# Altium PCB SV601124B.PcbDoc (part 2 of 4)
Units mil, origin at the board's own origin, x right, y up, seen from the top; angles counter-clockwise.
Board outline 3733 x 2734 mil, 4 copper layers (Top Layer, Mid-Layer 1, Mid-Layer 2, Bottom Layer), stack 60.2 mil thick; 246 components, 169 nets, 780 pads, 426 vias.
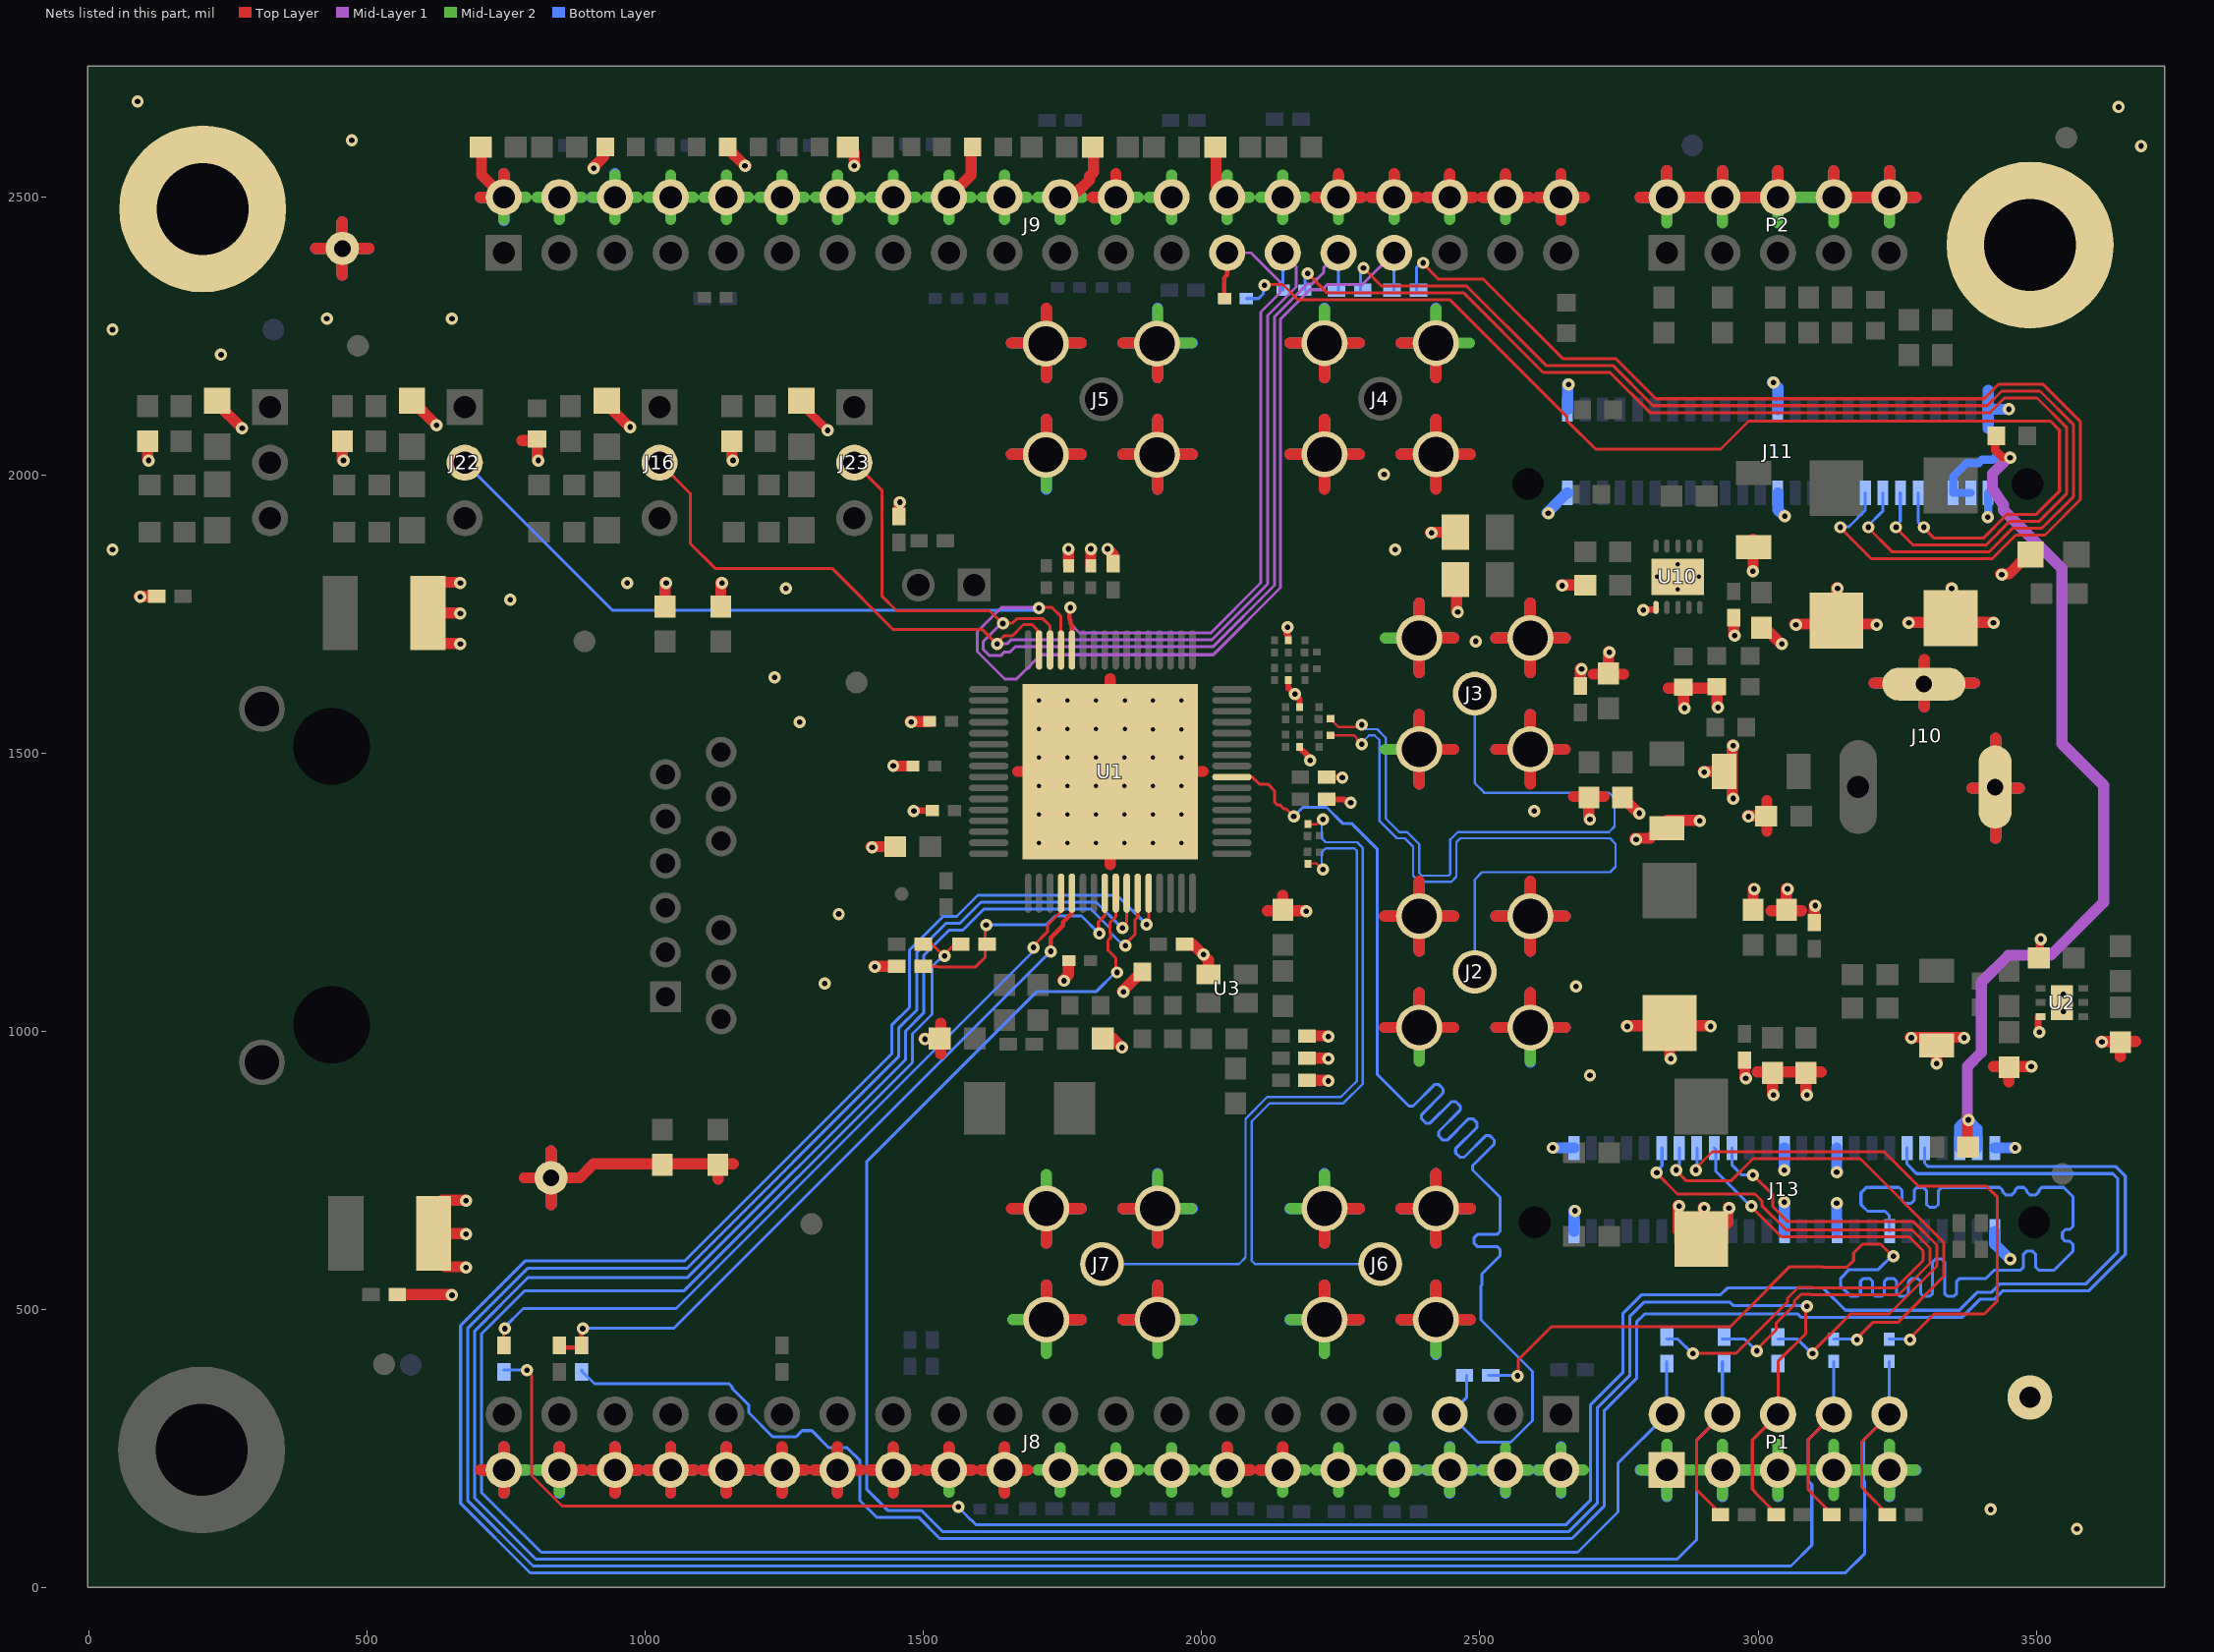
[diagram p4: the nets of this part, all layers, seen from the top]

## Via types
v1: diameter 22, hole 10, Top Layer to Bottom Layer, 385 vias
v2: diameter 19.68, hole 7.87, Top Layer to Bottom Layer, 40 vias
v3: diameter 20, hole 10, Top Layer to Bottom Layer, 1 vias

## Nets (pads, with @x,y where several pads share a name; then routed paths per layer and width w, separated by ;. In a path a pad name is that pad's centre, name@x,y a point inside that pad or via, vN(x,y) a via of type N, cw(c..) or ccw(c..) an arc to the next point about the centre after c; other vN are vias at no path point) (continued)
GND: C7.2 C8.2 C9.2 C10.2 C11.2 C12.1 C14.1 C15.1 C16.1 C17.2 C19.1 C53.2 C62.1 C70.1 C75.1 C80.2 C82.2 C87.1 C89.1 C90.1 C98.2 C104.1 C115.1 C128.2 C129.1 C133.2 C182.1 C183.2 C265.1 C267.1 C269.1 C270.1 C271.1 C272.1 C273.2 C274.2 C318.1 C319.1 C324.1 C325.1 C326.1 C327.1 C328.1 C329.1 C330.1 C331.1 C332.1 J2.2 J2.3 J2.4 J2.5 J3.2 J3.3 J3.4 J3.5 J4.2 J4.3 J4.4 J4.5 J5.2 J5.3 J5.4 J5.5 J6.2 J6.3 J6.4 J6.5 J7.2 J7.3 J7.4 J7.5 J8.2 J8.4 J8.6 J8.8 J8.10 J8.12 J8.14 J8.16 J8.18 J8.20 J8.22 J8.24 J8.26 J8.28 J8.30 J8.32 J8.34 J8.36 J8.38 J8.40 J9.2 J9.4 J9.6 J9.8 J9.10 J9.12 J9.14 J9.16 J9.18 J9.20 J9.22 J9.24 J9.26 J9.28 J9.30 J9.32 J9.34 J9.36 J9.38 J9.40 J10.2 J10.3 J11.1 J11.2 J11.25 J11.26 J11.49 J11.50 J13.1 J13.2 J13.19 J13.20 J13.25 J13.26 J13.49 J13.50 LD3.2 LD17.2 LD22.2 LD23.2 LD24.2 M200.1 M201.1 M202.1 P1.1 P1.3 P1.5 P1.7 P1.9 P2.2 P2.4 P2.6 P2.8 P2.10 pad.0 R2.1 R4.1 R6.1 R8.1 R11.1 R13.1 R16.1 R18.1 R20.1 R21.1 R25.1 R27.1 R29.1 R31.1 R34.1 R87.1 R97.2 R154.2 R177.1 R292.1 R352.2 R641.1 R645.1 R649.1 R661.1 U1.65 U2.3 U2.7 U3.2 U10.6 U10.11 | length 39013.7
  Top Layer w11: v1@1481,1397 C330.1@1516,1397 ; v1@2152.77,1727.22 2152.77,1715.01 2156,1711.78 R27.1@2156,1701.3 ; R29.1@2156,1632.7 2156,1617 2166,1607 2176,1597 R31.1@2176,1581.3 ; R34.1@2176,1512.7 2176,1510.24 2189.5,1496.74 2189.5,1494.72 2191,1493.22 2191,1490.45 v1@2193.45,1488 ; C327.1@2221,1417 2256,1417 2261,1412 v1@2266,1412 ; C328.1@2221,1457 v1@2251,1457 ; v1@2791.94,1757.94 U10.6@2816.63,1757.94
  Top Layer w12: v1@3503.47,999.53 U2.3@3503.47,1026.4
  Top Layer w15: LD23.2@1281,2133.34 1281,2127 v1(1328,2080) ; C129.1@3506,1132 v1@3506,1167
  Top Layer w20: v1@91,1782 R154.2@122.38,1782 ; v1@106,2027 R25.1@106,2062 ; LD24.2@231,2128 v1@274,2085 ; 407.98,2407 pad.0@456,2407 ; v1@456,2027 R18.1@456,2062 ; 456,2358.98 pad.0@456,2407 ; 456,2455.02 pad.0@456,2407 ; 504.02,2407 pad.0@456,2407 ; R352.2@554.62,527 v1@651,527 ; LD22.2@581,2132 LD22.2@581,2132.98 ; LD22.2@581,2133.34 v1(625,2089.34) ; v1@666,1697 626,1697 611.71,1711.29 C19.1@611.71,1752 ; v1@666,1752 C19.1@611.71,1752 ; v1@666,1807 631,1807 611.71,1787.71 C19.1@611.71,1752 ; v1@676,577 641,577 621.71,596.29 C115.1@621.71,637 ; v1@676,637 C115.1@621.71,637 ; v1@676.14,696.86 635.86,696.86 621.71,682.71 C115.1@621.71,637 ; 703.95,212 J8.40@746,212 ; 703.95,2499 J9.2@746,2499 ; R2.1@706,2589 706,2539 J9.2@746,2499 ; 746,169.95 J8.40@746,212 ; 746,254.05 J8.40@746,212 ; 746,2541.05 J9.2@746,2499 ; 778.48,2062 806,2062 v1@806,2027 ; 782.98,737 pad.0@831,737 ; 831,688.98 pad.0@831,737 ; 831,785.02 pad.0@831,737 ; 846,254.05 J8.38@846,212 888.05,212 ; 903.95,212 J8.36@946,212 ; v1@906,2552 926,2572 R4.1@926,2589 ; LD3.2@931,2127 v1@971,2087 ; 946,169.95 J8.36@946,212 ; 946,254.05 J8.36@946,212 ; 988.05,212 J8.36@946,212 ; 1003.95,212 J8.34@1046,212 ; C9.2@1036,1762 v1@1036,1807 ; 1046,169.95 J8.34@1046,212 ; 1046,254.05 J8.34@1046,212 ; 1088.05,212 J8.34@1046,212 ; 1103.95,212 J8.32@1146,212 ; 1131,734.48 C7.2@1131,762 ; C10.2@1136,1762 v1@1136,1807 ; 1146,169.95 J8.32@1146,212 ; 1146,254.05 J8.32@1146,212 ; R6.1@1146,2589 v1(1179.47,2555.53) v1@1181,2555.53 ; v1@1156,2027 R21.1@1156,2062 ; 1158.52,762 C7.2@1131,762 ; 1188.05,212 J8.32@1146,212 ; 1203.95,212 J8.30@1246,212 ; 1246,169.95 J8.30@1246,212 ; 1246,254.05 J8.30@1246,212 ; 1288.05,212 J8.30@1246,212 ; 1303.95,212 J8.28@1346,212 ; 1346,169.95 J8.28@1346,212 ; 1346,254.05 J8.28@1346,212 ; R8.1@1366,2589 1376,2579 v1(1376,2555.53) ; 1388.05,212 J8.28@1346,212 ; 1403.95,212 J8.26@1446,212 ; v1@1406,1332 R645.1@1451,1332 ; v1@1411,1117 C319.1@1456,1117 ; 1446,169.95 J8.26@1446,212 ; 1446,254.05 J8.26@1446,212 ; v1(1446,1477) C331.1@1481,1477 ; R661.1@1456,1922 v1@1456,1952 ; v1@1476,1557 C332.1@1511,1557 ; 1488.05,212 J8.26@1446,212 ; v1@1501,987 C273.2@1531,987 ; 1503.95,212 J8.24@1546,212 ; 1531,959.48 C273.2@1531,987 ; 1531,1014.52 C273.2@1531,987 ; 1546,254.05 J8.24@1546,212 ; J9.18@1546,2499 1586,2539 R11.1@1586,2589 ; 1588.05,212 J8.24@1546,212 ; 1603.95,212 J8.22@1646,212 ; 1646,169.95 J8.22@1646,212 ; 1646,254.05 J8.22@1646,212 ; 1658.48,682 J7.2@1721,682 ; 1658.48,2037 J5.3@1721,2037 ; 1658.48,2237 J5.2@1721,2237 ; 1670,1467 U1.65@1836,1467 ; 1688.05,212 J8.22@1646,212 ; 1721,544.52 J7.3@1721,482 1783.52,482 ; 1721,619.48 J7.2@1721,682 ; 1721,2099.52 J5.3@1721,2037 ; 1721,2174.48 J5.2@1721,2237 ; 1721,2299.52 J5.2@1721,2237 ; J9.22@1746,2499 1761.23,2499 1769.8,2507.57 1774.76,2507.57 1781.19,2514 1782.6,2514 1799,2530.4 1799,2536.77 1806,2543.77 R13.1@1806,2589 ; v1@1751,1092 1761,1102 C325.1@1761,1127 ; C318.1@1761,1837 v1(1761,1867) ; 1783.52,682 J7.2@1721,682 ; 1783.52,2037 J5.3@1721,2037 ; 1783.52,2237 J5.2@1721,2237 ; C324.1@1801,1837 v1(1801,1867) ; 1803.95,2499 J9.24@1846,2499 1846,2541.05 ; C274.2@1821,987 1841,987 1855,973 v1@1855,972 ; v1(1831,1867) 1841,1857 C329.1@1841,1837 ; 1836,1300 U1.65@1836,1467 ; 1836,1634 U1.65@1836,1467 ; v1@1857.53,1072 R649.1@1891,1105.47 ; 1858.48,482 J7.4@1921,482 1921,544.52 ; 1858.48,682 J7.5@1921,682 1921,619.48 ; 1858.48,2037 J5.4@1921,2037 ; 1858.48,2237 1921,2237 1921,2174.48 ; 1921,1974.48 J5.4@1921,2037 ; 1921,2099.52 J5.4@1921,2037 ; C326.1@1966,1157 1983.79,1157 2001.3,1139.49 2012.5,1128.29 U3.2@2012.5,1102.51 ; 1983.52,2037 J5.4@1921,2037 ; 2003,1467 U1.65@1836,1467 ; R292.1@2026,2589 2026,2519 J9.28@2046,2499 ; 2046,254.05 J8.14@2046,212 2088.05,212 ; 2103.95,212 J8.12@2146,212 2146,254.05 ; 2118.48,1217 R97.2@2146,1217 ; 2146,1244.52 R97.2@2146,1217 ; 2158.48,2037 J4.3@2221,2037 ; 2158.48,2237 J4.2@2221,2237 ; C271.1@2186,912 v1@2226,912 ; C272.1@2186,952 v1@2226,952 ; C270.1@2186,992 v1@2226,992 ; v1@2186,1217 R97.2@2146,1217 ; 2203.95,2499 J9.32@2246,2499 ; 2221,544.52 J6.3@2221,482 2283.52,482 ; 2221,619.48 J6.2@2221,682 2283.52,682 ; 2221,1974.48 J4.3@2221,2037 ; 2221,2099.52 J4.3@2221,2037 ; 2221,2174.48 J4.2@2221,2237 ; 2246,2541.05 J9.32@2246,2499 ; 2283.52,2037 J4.3@2221,2037 ; 2283.52,2237 J4.2@2221,2237 ; 2288.05,2499 J9.32@2246,2499 ; 2303.95,2499 J9.34@2346,2499 ; 2328.48,1007 J2.3@2391,1007 ; 2328.48,1207 J2.2@2391,1207 ; 2346,2541.05 J9.34@2346,2499 ; 2358.48,482 J6.4@2421,482 ; 2358.48,682 J6.5@2421,682 ; 2358.48,2037 J4.4@2421,2037 ; 2358.48,2237 J4.5@2421,2237 2421,2174.48 ; 2388.05,2499 J9.34@2346,2499 ; 2391,1069.52 J2.3@2391,1007 ; 2391,1144.48 J2.2@2391,1207 ; 2391,1269.52 J2.2@2391,1207 ; 2391,1444.48 J3.3@2391,1507 ; 2391,1569.52 J3.3@2391,1507 ; 2391,1644.48 J3.2@2391,1707 ; 2391,1769.52 J3.2@2391,1707 ; 2403.95,2499 J9.36@2446,2499 ; v1@2411,1897 C87.1@2458.52,1897 ; 2421,544.52 J6.4@2421,482 ; 2421,619.48 J6.5@2421,682 ; 2421,744.52 J6.5@2421,682 ; 2421,1974.48 J4.4@2421,2037 ; 2421,2099.52 J4.4@2421,2037 ; 2446,2541.05 J9.36@2446,2499 ; 2453.52,1007 J2.3@2391,1007 ; 2453.52,1207 J2.2@2391,1207 ; 2453.52,1507 J3.3@2391,1507 ; 2453.52,1707 J3.2@2391,1707 ; v1@2458.52,1754.48 C98.2@2458.52,1812 ; 2483.52,482 J6.4@2421,482 ; 2483.52,682 J6.5@2421,682 ; 2483.52,2037 J4.4@2421,2037 ; 2488.05,2499 J9.36@2446,2499 ; 2503.95,2499 J9.38@2546,2499 ; 2528.48,1007 J2.4@2591,1007 ; 2528.48,1207 J2.5@2591,1207 ; 2528.48,1507 J3.4@2591,1507 ; 2528.48,1707 J3.5@2591,1707 ; 2546,2541.05 J9.38@2546,2499 ; 2588.05,2499 J9.38@2546,2499 ; 2591,1069.52 J2.4@2591,1007 ; 2591,1144.48 J2.5@2591,1207 ; 2591,1269.52 J2.5@2591,1207 ; 2591,1444.48 J3.4@2591,1507 ; 2591,1569.52 J3.4@2591,1507 ; 2591,1644.48 J3.5@2591,1707 ; 2591,1769.52 J3.5@2591,1707 ; 2603.95,2499 J9.40@2646,2499 ; v1@2646,1802 R20.1@2691,1802 ; 2646,2456.95 J9.40@2646,2499 ; 2646,2541.05 J9.40@2646,2499 ; 2653.52,1007 J2.4@2591,1007 ; 2653.52,1207 J2.5@2591,1207 ; 2653.52,1507 J3.4@2591,1507 ; 2653.52,1707 J3.5@2591,1707 ; 2668.48,1422 C265.1@2696,1422 ; C269.1@2681,1617 v1@2681,1652 ; 2688.05,2499 J9.40@2646,2499 ; v1@2696,1382 C265.1@2696,1422 ; 2703.48,1642 C267.1@2731,1642 ; 2723.52,1422 C265.1@2696,1422 ; v1@2731,1682 C267.1@2731,1642 ; C53.2@2756,1422 2766,1412 2766,1411 2784,1393 v1@2785,1393 ; 2758.52,1642 C267.1@2731,1642 ; v1@2763.01,1009.99 C17.2@2841,1009.99 ; v1@2779,1346 2779,1347 2806,1347 2836,1377 2836,1379.48 v1@2893.52,1379.48 ; 2787.98,2499 P2.2@2836,2499 ; 2836,2547.02 P2.2@2836,2499 ; 2838.48,1617 C104.1@2866,1617 ; v1@2841,952 C17.2@2841,1009.99 ; v1@2856.16,686.97 2856,686.81 2856,642 2878.01,619.99 C80.2@2901,619.99 ; v1@2866,1582 C104.1@2866,1617 ; 2884.02,2499 P2.2@2836,2499 ; 2887.98,2499 P2.4@2936,2499 ; 2893.52,1617 C104.1@2866,1617 ; 2898.48,1617 2926,1617 v1@2926,1583 ; v1@2901,683.48 C80.2@2901,619.99 ; v1@2901,1467 C82.2@2953.48,1467 ; v1@2913.01,1009.99 C17.2@2841,1009.99 ; 2936,2547.02 P2.4@2936,2499 ; v1@2946,683.49 2946,657 2908.99,619.99 C80.2@2901,619.99 ; v1@2953.48,1419.52 C82.2@2953.48,1467 ; v1@2953.48,1514.48 C82.2@2953.48,1467 ; v1@2956,1712 C182.1@2956,1747 ; v1@2976,917 C75.1@2976,952 ; v1@2981,1387 C89.1@3016,1387 ; 2984.02,2499 P2.4@2936,2499 ; 2987.98,2499 P2.6@3036,2499 3036,2547.02 ; C14.1@2991,1217 v1@2991,1257 ; v1(2991,1827) C12.1@2991,1884.48 ; 2998.48,927 C70.1@3026,927 ; C90.1@3006,1727 3011,1727 v1@3041,1697 ; 3016,1359.48 C89.1@3016,1387 ; 3016,1414.52 C89.1@3016,1387 ; 3023.48,1217 C15.1@3051,1217 ; v1@3026,887 C70.1@3026,927 ; v1@3051,1257 C15.1@3051,1217 ; v1@3066.01,1731.99 C128.2@3141,1731.99 ; 3078.52,1217 C15.1@3051,1217 ; v1@3086,887 C62.1@3086,927 ; C16.1@3101,1192 v1@3101,1227 ; 3113.52,927 C62.1@3086,927 ; 3136,2547.02 P2.8@3136,2499 3184.02,2499 ; v1@3141,1797 C128.2@3141,1731.99 ; 3187.98,2499 P2.10@3236,2499 ; 3208.98,1626 J10.3@3299,1626 ; v1@3210.99,1731.99 C128.2@3141,1731.99 ; 3236,2547.02 P2.10@3236,2499 ; v1@3268.99,1734.99 C183.2@3346,1734.99 ; v1@3273.48,989.48 C133.2@3321,989.48 ; 3284.02,2499 P2.10@3236,2499 ; 3299,1583.48 J10.3@3299,1626 ; 3299,1668.52 J10.3@3299,1626 ; v1(3321,942) C133.2@3321,989.48 ; v1@3346,1797 C183.2@3346,1734.99 ; v1@3368.48,989.48 C133.2@3321,989.48 ; 3384.48,1437 J10.2@3427,1437 ; 3389.02,1626 J10.3@3299,1626 ; v1@3421,1734.99 C183.2@3346,1734.99 ; 3423.48,937 R87.1@3451,937 ; 3427,1346.98 J10.2@3427,1437 ; 3427,1527.02 J10.2@3427,1437 ; v1@3436,1822 3451,1822 3486,1857 LD17.2@3490.02,1857 ; 3451,909.48 R87.1@3451,937 ; 3469.52,1437 J10.2@3427,1437 ; v1(3491,937) R87.1@3451,937 ; v1@3616,982 R177.1@3651,982 ; 3651,954.48 R177.1@3651,982 ; 3678.52,982 R177.1@3651,982 ; pad.0@831,737 882.5,737 907.5,762 C7.2@1131,762 ; C70.1@3026,927 C62.1@3086,927
  Mid-Layer 2 w20: 409.98,2407 pad.0@456,2407 ; 456,2360.98 pad.0@456,2407 ; 456,2453.02 pad.0@456,2407 ; 502.02,2407 pad.0@456,2407 ; 705.95,212 J8.40@746,212 ; 705.95,2499 J9.2@746,2499 ; 746,171.95 J8.40@746,212 ; 746,252.05 J8.40@746,212 ; 746,2458.95 J9.2@746,2499 ; 746,2539.05 J9.2@746,2499 ; 784.98,737 pad.0@831,737 ; 786.05,212 J8.40@746,212 ; 786.05,2499 J9.2@746,2499 ; 805.95,212 J8.38@846,212 ; 805.95,2499 J9.4@846,2499 ; 831,690.98 pad.0@831,737 ; 831,783.02 pad.0@831,737 ; 846,171.95 J8.38@846,212 ; 846,252.05 J8.38@846,212 ; 846,2458.95 J9.4@846,2499 ; 877.02,737 pad.0@831,737 ; 886.05,212 J8.38@846,212 ; 886.05,2499 J9.4@846,2499 ; 905.95,212 J8.36@946,212 ; 905.95,2499 J9.6@946,2499 ; 946,171.95 J8.36@946,212 ; 946,252.05 J8.36@946,212 ; 946,2458.95 J9.6@946,2499 ; 946,2539.05 J9.6@946,2499 ; 986.05,212 J8.36@946,212 ; 986.05,2499 J9.6@946,2499 ; 1005.95,212 J8.34@1046,212 ; 1005.95,2499 J9.8@1046,2499 ; 1046,171.95 J8.34@1046,212 ; 1046,252.05 J8.34@1046,212 ; 1046,2458.95 J9.8@1046,2499 ; 1046,2539.05 J9.8@1046,2499 ; 1086.05,212 J8.34@1046,212 ; 1086.05,2499 J9.8@1046,2499 ; 1105.95,212 J8.32@1146,212 ; 1105.95,2499 J9.10@1146,2499 ; 1146,171.95 J8.32@1146,212 ; 1146,252.05 J8.32@1146,212 ; 1146,2458.95 J9.10@1146,2499 ; 1146,2539.05 J9.10@1146,2499 ; 1186.05,212 J8.32@1146,212 ; 1186.05,2499 J9.10@1146,2499 ; 1205.95,212 J8.30@1246,212 ; 1205.95,2499 J9.12@1246,2499 ; 1246,171.95 J8.30@1246,212 ; 1246,252.05 J8.30@1246,212 ; 1246,2458.95 J9.12@1246,2499 ; 1246,2539.05 J9.12@1246,2499 ; 1286.05,212 J8.30@1246,212 ; 1286.05,2499 J9.12@1246,2499 ; 1305.95,212 J8.28@1346,212 ; 1305.95,2499 J9.14@1346,2499 ; 1346,171.95 J8.28@1346,212 ; 1346,252.05 J8.28@1346,212 ; 1346,2458.95 J9.14@1346,2499 ; 1346,2539.05 J9.14@1346,2499 ; 1386.05,212 J8.28@1346,212 ; 1386.05,2499 J9.14@1346,2499 ; 1405.95,212 J8.26@1446,212 ; 1405.95,2499 J9.16@1446,2499 ; 1446,171.95 J8.26@1446,212 ; 1446,252.05 J8.26@1446,212 ; 1446,2458.95 J9.16@1446,2499 ; 1446,2539.05 J9.16@1446,2499 ; 1486.05,212 J8.26@1446,212 ; 1486.05,2499 J9.16@1446,2499 ; 1505.95,212 J8.24@1546,212 ; 1505.95,2499 J9.18@1546,2499 ; 1546,171.95 J8.24@1546,212 ; 1546,252.05 J8.24@1546,212 ; 1546,2458.95 J9.18@1546,2499 ; 1546,2539.05 J9.18@1546,2499 ; 1586.05,212 J8.24@1546,212 ; 1586.05,2499 J9.18@1546,2499 ; 1605.95,212 J8.22@1646,212 ; 1605.95,2499 J9.20@1646,2499 ; 1646,171.95 J8.22@1646,212 ; 1646,252.05 J8.22@1646,212 ; 1646,2458.95 J9.20@1646,2499 ; 1646,2539.05 J9.20@1646,2499 ; 1660.48,482 J7.3@1721,482 ; 1660.48,682 J7.2@1721,682 ; 1660.48,2037 J5.3@1721,2037 ; 1660.48,2237 J5.2@1721,2237 ; 1686.05,212 J8.22@1646,212 ; 1686.05,2499 J9.20@1646,2499 ; 1705.95,212 J8.20@1746,212 ; 1705.95,2499 J9.22@1746,2499 ; 1721,421.48 J7.3@1721,482 ; 1721,542.52 J7.3@1721,482 ; 1721,621.48 J7.2@1721,682 ; 1721,742.52 J7.2@1721,682 ; 1721,1976.48 J5.3@1721,2037 ; 1721,2097.52 J5.3@1721,2037 ; 1721,2176.48 J5.2@1721,2237 ; 1721,2297.52 J5.2@1721,2237 ; 1746,171.95 J8.20@1746,212 ; 1746,252.05 J8.20@1746,212 ; 1746,2458.95 J9.22@1746,2499 ; 1781.52,482 J7.3@1721,482 ; 1781.52,682 J7.2@1721,682 ; 1781.52,2037 J5.3@1721,2037 ; 1781.52,2237 J5.2@1721,2237 ; 1786.05,212 J8.20@1746,212 ; 1786.05,2499 J9.22@1746,2499 ; 1805.95,212 J8.18@1846,212 ; 1805.95,2499 J9.24@1846,2499 ; 1846,171.95 J8.18@1846,212 ; 1846,252.05 J8.18@1846,212 ; 1846,2458.95 J9.24@1846,2499 ; 1846,2539.05 J9.24@1846,2499 ; 1860.48,482 J7.4@1921,482 ; 1860.48,682 J7.5@1921,682 ; 1860.48,2037 J5.4@1921,2037 ; 1860.48,2237 J5.5@1921,2237 ; 1886.05,212 J8.18@1846,212 ; 1886.05,2499 J9.24@1846,2499 ; 1905.95,212 J8.16@1946,212 ; 1905.95,2499 J9.26@1946,2499 ; 1921,421.48 J7.4@1921,482 ; 1921,542.52 J7.4@1921,482 ; 1921,621.48 J7.5@1921,682 ; 1921,742.52 J7.5@1921,682 ; 1921,1976.48 J5.4@1921,2037 ; 1921,2097.52 J5.4@1921,2037 ; 1921,2176.48 J5.5@1921,2237 ; 1921,2297.52 J5.5@1921,2237 ; 1946,171.95 J8.16@1946,212 ; 1946,252.05 J8.16@1946,212 ; 1946,2458.95 J9.26@1946,2499 ; 1946,2539.05 J9.26@1946,2499 ; 1981.52,482 J7.4@1921,482 ; 1981.52,682 J7.5@1921,682 ; 1981.52,2037 J5.4@1921,2037 ; 1981.52,2237 J5.5@1921,2237 ; 1986.05,212 J8.16@1946,212 ; 2005.95,212 J8.14@2046,212 ; 2046,171.95 J8.14@2046,212 ; 2046,252.05 J8.14@2046,212 ; 2046,2458.95 J9.28@2046,2499 ; 2046,2539.05 J9.28@2046,2499 ; 2086.05,212 J8.14@2046,212 ; 2086.05,2499 J9.28@2046,2499 ; 2105.95,212 J8.12@2146,212 ; 2105.95,2499 J9.30@2146,2499 ; 2146,171.95 J8.12@2146,212 ; 2146,252.05 J8.12@2146,212 ; 2146,2458.95 J9.30@2146,2499 ; 2146,2539.05 J9.30@2146,2499 ; 2160.48,482 J6.3@2221,482 ; 2160.48,682 J6.2@2221,682 ; 2160.48,2037 J4.3@2221,2037 ; 2160.48,2237 J4.2@2221,2237 ; 2186.05,212 J8.12@2146,212 ; 2186.05,2499 J9.30@2146,2499 ; 2205.95,212 J8.10@2246,212 ; 2205.95,2499 J9.32@2246,2499 ; 2221,421.48 J6.3@2221,482 ; 2221,542.52 J6.3@2221,482 ; 2221,621.48 J6.2@2221,682 ; 2221,742.52 J6.2@2221,682 ; 2221,1976.48 J4.3@2221,2037 ; 2221,2097.52 J4.3@2221,2037 ; 2221,2176.48 J4.2@2221,2237 ; 2221,2297.52 J4.2@2221,2237 ; 2246,171.95 J8.10@2246,212 ; 2246,252.05 J8.10@2246,212 ; 2246,2458.95 J9.32@2246,2499 ; 2246,2539.05 J9.32@2246,2499 ; 2281.52,482 J6.3@2221,482 ; 2281.52,682 J6.2@2221,682 ; 2281.52,2037 J4.3@2221,2037 ; 2281.52,2237 J4.2@2221,2237 ; 2286.05,212 J8.10@2246,212 ; 2286.05,2499 J9.32@2246,2499 ; 2305.95,212 J8.8@2346,212 ; 2305.95,2499 J9.34@2346,2499 ; 2330.48,1007 J2.3@2391,1007 ; 2330.48,1207 J2.2@2391,1207 ; 2330.48,1507 J3.3@2391,1507 ; 2330.48,1707 J3.2@2391,1707 ; 2346,171.95 J8.8@2346,212 ; 2346,252.05 J8.8@2346,212 ; 2346,2458.95 J9.34@2346,2499 ; 2346,2539.05 J9.34@2346,2499 ; 2360.48,482 J6.4@2421,482 ; 2360.48,682 J6.5@2421,682 ; 2360.48,2037 J4.4@2421,2037 ; 2360.48,2237 J4.5@2421,2237 ; 2386.05,212 J8.8@2346,212 ; 2386.05,2499 J9.34@2346,2499 ; 2391,946.48 J2.3@2391,1007 ; 2391,1067.52 J2.3@2391,1007 ; 2391,1146.48 J2.2@2391,1207 ; 2391,1267.52 J2.2@2391,1207 ; 2391,1446.48 J3.3@2391,1507 ; 2391,1567.52 J3.3@2391,1507 ; 2391,1646.48 J3.2@2391,1707 ; 2391,1767.52 J3.2@2391,1707 ; 2405.95,212 J8.6@2446,212 ; 2405.95,2499 J9.36@2446,2499 ; 2421,421.48 J6.4@2421,482 ; 2421,542.52 J6.4@2421,482 ; 2421,621.48 J6.5@2421,682 ; 2421,742.52 J6.5@2421,682 ; 2421,1976.48 J4.4@2421,2037 ; 2421,2097.52 J4.4@2421,2037 ; 2421,2176.48 J4.5@2421,2237 ; 2421,2297.52 J4.5@2421,2237 ; 2446,171.95 J8.6@2446,212 ; 2446,252.05 J8.6@2446,212 ; 2446,2458.95 J9.36@2446,2499 ; 2446,2539.05 J9.36@2446,2499 ; 2451.52,1007 J2.3@2391,1007 ; 2451.52,1207 J2.2@2391,1207 ; 2451.52,1507 J3.3@2391,1507 ; 2451.52,1707 J3.2@2391,1707 ; 2481.52,482 J6.4@2421,482 ; 2481.52,682 J6.5@2421,682 ; 2481.52,2037 J4.4@2421,2037 ; 2481.52,2237 J4.5@2421,2237 ; 2486.05,212 J8.6@2446,212 ; 2486.05,2499 J9.36@2446,2499 ; 2505.95,212 J8.4@2546,212 ; 2505.95,2499 J9.38@2546,2499 ; 2530.48,1007 J2.4@2591,1007 ; 2530.48,1207 J2.5@2591,1207 ; 2530.48,1507 J3.4@2591,1507 ; 2530.48,1707 J3.5@2591,1707 ; 2546,171.95 J8.4@2546,212 ; 2546,252.05 J8.4@2546,212 ; 2546,2458.95 J9.38@2546,2499 ; 2546,2539.05 J9.38@2546,2499 ; 2586.05,212 J8.4@2546,212 ; 2586.05,2499 J9.38@2546,2499 ; 2591,946.48 J2.4@2591,1007 ; 2591,1067.52 J2.4@2591,1007 ; 2591,1146.48 J2.5@2591,1207 ; 2591,1267.52 J2.5@2591,1207 ; 2591,1446.48 J3.4@2591,1507 ; 2591,1567.52 J3.4@2591,1507 ; 2591,1646.48 J3.5@2591,1707 ; 2591,1767.52 J3.5@2591,1707 ; 2605.95,212 J8.2@2646,212 ; 2605.95,2499 J9.40@2646,2499 ; 2646,171.95 J8.2@2646,212 ; 2646,252.05 J8.2@2646,212 ; 2646,2458.95 J9.40@2646,2499 ; 2646,2539.05 J9.40@2646,2499 ; 2651.52,1007 J2.4@2591,1007 ; 2651.52,1207 J2.5@2591,1207 ; 2651.52,1507 J3.4@2591,1507 ; 2651.52,1707 J3.5@2591,1707 ; 2686.05,212 J8.2@2646,212 ; 2686.05,2499 J9.40@2646,2499 ; 2789.98,212 P1.1@2836,212 ; 2789.98,2499 P2.2@2836,2499 ; 2836,165.98 P1.1@2836,212 ; 2836,258.02 P1.1@2836,212 ; 2836,2452.98 P2.2@2836,2499 ; 2836,2545.02 P2.2@2836,2499 ; 2882.02,212 P1.1@2836,212 ; 2882.02,2499 P2.2@2836,2499 ; 2889.98,212 P1.3@2936,212 ; 2889.98,2499 P2.4@2936,2499 ; 2936,165.98 P1.3@2936,212 ; 2936,258.02 P1.3@2936,212 ; 2936,2452.98 P2.4@2936,2499 ; 2936,2545.02 P2.4@2936,2499 ; 2982.02,212 P1.3@2936,212 ; 2982.02,2499 P2.4@2936,2499 ; 2989.98,212 P1.5@3036,212 ; 2989.98,2499 P2.6@3036,2499 ; 3036,165.98 P1.5@3036,212 ; 3036,258.02 P1.5@3036,212 ; 3036,2452.98 P2.6@3036,2499 ; 3036,2545.02 P2.6@3036,2499 ; 3082.02,212 P1.5@3036,212 ; 3082.02,2499 P2.6@3036,2499 ; 3089.98,212 P1.7@3136,212 ; 3089.98,2499 P2.8@3136,2499 ; 3136,165.98 P1.7@3136,212 ; 3136,258.02 P1.7@3136,212 ; 3136,2452.98 P2.8@3136,2499 ; 3136,2545.02 P2.8@3136,2499 ; 3182.02,212 P1.7@3136,212 ; 3182.02,2499 P2.8@3136,2499 ; 3189.98,212 P1.9@3236,212 ; 3189.98,2499 P2.10@3236,2499 ; 3210.98,1626 J10.3@3299,1626 ; 3236,165.98 P1.9@3236,212 ; 3236,258.02 P1.9@3236,212 ; 3236,2452.98 P2.10@3236,2499 ; 3236,2545.02 P2.10@3236,2499 ; 3282.02,212 P1.9@3236,212 ; 3282.02,2499 P2.10@3236,2499 ; 3299,1585.48 J10.3@3299,1626 ; 3299,1666.52 J10.3@3299,1626 ; 3386.48,1437 J10.2@3427,1437 ; 3387.02,1626 J10.3@3299,1626 ; 3427,1348.98 J10.2@3427,1437 ; 3427,1525.02 J10.2@3427,1437 ; 3467.52,1437 J10.2@3427,1437
  Bottom Layer w15: v1@3413.55,1924.45 J11.2@3413.55,1967.58
  Bottom Layer w20: 407.98,2407 pad.0@456,2407 ; 456,2358.98 pad.0@456,2407 ; 456,2455.02 pad.0@456,2407 ; 504.02,2407 pad.0@456,2407 ; 703.95,2499 J9.2@746,2499 ; 746,169.95 J8.40@746,212 ; 746,254.05 J8.40@746,212 ; 746,2456.95 J9.2@746,2499 ; 746,2541.05 J9.2@746,2499 ; 782.98,737 pad.0@831,737 ; 788.05,212 J8.40@746,212 ; 803.95,212 J8.38@846,212 ; 831,688.98 pad.0@831,737 ; 831,785.02 pad.0@831,737 ; 846,169.95 J8.38@846,212 ; 846,254.05 J8.38@846,212 ; 879.02,737 pad.0@831,737 ; 888.05,212 J8.38@846,212 ; 903.95,212 J8.36@946,212 ; 903.95,2499 J9.6@946,2499 946,2541.05 ; 946,169.95 J8.36@946,212 ; 946,254.05 J8.36@946,212 ; 988.05,212 J8.36@946,212 ; 1003.95,212 J8.34@1046,212 ; 1046,169.95 J8.34@1046,212 ; 1046,254.05 J8.34@1046,212 ; 1088.05,212 J8.34@1046,212 ; 1103.95,212 J8.32@1146,212 ; 1146,169.95 J8.32@1146,212 ; 1146,254.05 J8.32@1146,212 ; 1188.05,212 J8.32@1146,212 ; 1203.95,212 J8.30@1246,212 1246,169.95 ; 1658.48,2037 J5.3@1721,2037 ; 1658.48,2237 J5.2@1721,2237 ; 1721,544.52 J7.3@1721,482 1783.52,482 ; 1721,619.48 J7.2@1721,682 1783.52,682 ; 1721,1974.48 J5.3@1721,2037 ; 1721,2099.52 J5.3@1721,2037 ; 1721,2174.48 J5.2@1721,2237 ; 1783.52,2037 J5.3@1721,2037 ; 1783.52,2237 J5.2@1721,2237 ; 1858.48,482 J7.4@1921,482 ; 1858.48,682 J7.5@1921,682 ; 1858.48,2037 J5.4@1921,2037 ; 1858.48,2237 J5.5@1921,2237 ; 1921,544.52 J7.4@1921,482 ; 1921,619.48 J7.5@1921,682 ; 1921,744.52 J7.5@1921,682 ; 1921,1974.48 J5.4@1921,2037 ; 1921,2099.52 J5.4@1921,2037 ; 1921,2174.48 J5.5@1921,2237 ; 1921,2299.52 J5.5@1921,2237 ; 1983.52,482 J7.4@1921,482 ; 1983.52,682 J7.5@1921,682 ; 1983.52,2037 J5.4@1921,2037 ; 1983.52,2237 J5.5@1921,2237 ; 2158.48,482 J6.3@2221,482 ; 2158.48,682 J6.2@2221,682 ; 2158.48,2037 J4.3@2221,2037 ; 2158.48,2237 J4.2@2221,2237 ; 2221,544.52 J6.3@2221,482 ; 2221,619.48 J6.2@2221,682 ; 2221,744.52 J6.2@2221,682 ; 2221,2099.52 J4.3@2221,2037 ; 2221,2174.48 J4.2@2221,2237 ; 2221,2299.52 J4.2@2221,2237 ; 2283.52,482 J6.3@2221,482 ; 2283.52,682 J6.2@2221,682 ; 2283.52,2037 J4.3@2221,2037 ; 2283.52,2237 J4.2@2221,2237 ; 2346,254.05 J8.8@2346,212 2388.05,212 ; 2358.48,482 J6.4@2421,482 ; 2358.48,682 J6.5@2421,682 ; 2358.48,2037 J4.4@2421,2037 2421,2099.52 ; 2358.48,2237 J4.5@2421,2237 ; 2391,1069.52 J2.3@2391,1007 2453.52,1007 ; 2391,1144.48 J2.2@2391,1207 2453.52,1207 ; 2391,1444.48 J3.3@2391,1507 ; 2391,1569.52 J3.3@2391,1507 ; 2391,1644.48 J3.2@2391,1707 ; 2391,1769.52 J3.2@2391,1707 ; 2403.95,212 J8.6@2446,212 ; 2421,419.48 J6.4@2421,482 ; 2421,544.52 J6.4@2421,482 ; 2421,619.48 J6.5@2421,682 ; 2421,744.52 J6.5@2421,682 ; 2421,2174.48 J4.5@2421,2237 ; 2421,2299.52 J4.5@2421,2237 ; 2446,169.95 J8.6@2446,212 ; 2446,254.05 J8.6@2446,212 ; 2453.52,1507 J3.3@2391,1507 ; 2453.52,1707 J3.2@2391,1707 ; 2483.52,682 J6.5@2421,682 ; 2488.05,212 J8.6@2446,212 ; 2503.95,212 J8.4@2546,212 ; 2528.48,1007 J2.4@2591,1007 ; 2528.48,1207 J2.5@2591,1207 ; 2528.48,1507 J3.4@2591,1507 2591,1569.52 ; 2528.48,1707 J3.5@2591,1707 ; 2546,169.95 J8.4@2546,212 ; 2588.05,212 J8.4@2546,212 ; 2591,944.48 J2.4@2591,1007 ; 2591,1069.52 J2.4@2591,1007 ; 2591,1144.48 J2.5@2591,1207 ; 2591,1644.48 J3.5@2591,1707 ; 2591,1769.52 J3.5@2591,1707 ; 2603.95,212 J8.2@2646,212 ; v1@2621,1932 2656.58,1967.58 J11.50@2657.55,1967.58 ; v1(2631,790.8) J13.49@2669.36,790.8 ; 2646,169.95 J8.2@2646,212 ; 2646,254.05 J8.2@2646,212 ; 2653.52,1007 J2.4@2591,1007 ; 2653.52,1207 J2.5@2591,1207 ; 2653.52,1707 J3.5@2591,1707 ; J11.49@2657.55,2117.58 v1@2657.55,2163.55 ; J13.50@2669.36,640.8 v1@2669.36,678.64 ; 2787.98,212 P1.1@2836,212 2836,163.98 ; 2787.98,2499 P2.2@2836,2499 ; 2836,2547.02 P2.2@2836,2499 ; 2884.02,2499 P2.2@2836,2499 ; 2887.98,2499 P2.4@2936,2499 ; 2936,163.98 P1.3@2936,212 2984.02,212 ; 2936,2547.02 P2.4@2936,2499 ; 2984.02,2499 P2.4@2936,2499 ; 2987.98,212 P1.5@3036,212 3036,163.98 ; 2987.98,2499 P2.6@3036,2499 ; v1@3026,2167 3035.55,2157.45 J11.25@3035.55,2117.58 ; J11.26@3035.55,1967.58 3035.55,1937.45 v1@3046,1927 ; 3036,2547.02 P2.6@3036,2499 ; J13.26@3047.36,640.8 v1(3047.36,693.36) ; v1(3047.36,750.64) J13.25@3047.36,790.8 ; 3084.02,2499 P2.6@3036,2499 ; 3087.98,2499 P2.8@3136,2499 ; 3136,2547.02 P2.8@3136,2499 ; J13.20@3141.36,640.8 v1(3141.36,691.64) ; v1(3141.36,747) J13.19@3141.36,790.8 ; 3184.02,2499 P2.8@3136,2499 ; 3187.98,2499 P2.10@3236,2499 ; 3208.98,1626 J10.3@3299,1626 ; 3236,163.98 P1.9@3236,212 3284.02,212 ; 3236,2547.02 P2.10@3236,2499 ; 3284.02,2499 P2.10@3236,2499 ; 3299,1583.48 J10.3@3299,1626 ; 3384.48,1437 J10.2@3427,1437 ; 3389.02,1626 J10.3@3299,1626 ; 3413.55,2083.37 J11.1@3413.55,2117.58 ; 3413.55,2151.79 J11.1@3413.55,2117.58 ; J13.2@3425.36,640.8 3425.36,617.64 v1@3451,592 ; J13.1@3425.36,790.8 v1(3462.2,790.8) ; 3427,1346.98 J10.2@3427,1437 ; 3427,1527.02 J10.2@3427,1437 ; v1(3451,2118) 3413.97,2118 J11.1@3413.55,2117.58 ; 3469.52,1437 J10.2@3427,1437
  other v1: 3573,106 3418,141 653,526 678,576 3453,591 678,636 2671.36,677.64 2903,682.48 2948,682.49 2858.16,685.97 678.14,695.86 3028,886 3088,886 2228,911 2978,916 2698,921 2228,951 2843,951 1857,971 3618,981 1503,986 3275.48,988.48 3370.48,988.48 2228,991 3505.47,998.53 2765.01,1008.99 2915.01,1008.99 3549,1036 3549,1067 1859.53,1071 2673,1081 1323,1086 1753,1091 1413,1116 2003.3,1138.49 3508,1166 1348,1211 2188,1216 3103,1226 2993,1256 3053,1256 1408,1331 2781,1345 2895.52,1378.48 2698,1381 2983,1386 2787,1392 1483,1396 2598,1396 2268,1411 2955.48,1418.52 2253,1456 2903,1466 2195.45,1487 2955.48,1513.48 1278,1556 1478,1556 2868,1581 2928,1582 2168,1606 1233,1636 2683,1651 2733,1681 668,1696 3043,1696 2493,1701 2958,1711 2154.77,1726.22 3068.01,1730.99 3212.99,1730.99 3270.99,1733.99 3423,1733.99 668,1751 2460.52,1753.48 2793.94,1756.94 758,1776 93,1781 1253,1796 3143,1796 3348,1796 2648,1801 668,1806 968,1806 1038,1806 1138,1806 3438,1821 43,1866 2348,1866 2413,1896 3413,1924 3048,1926 2623,1931 1458,1951 2328,2001 108,2026 458,2026 808,2026 1158,2026 276,2084 973.39,2086 2659.55,2162.55 3028,2166 238,2216 43,2261 428,2281 653,2281 908,2551 3688,2591 473,2601 3648,2661 88,2671
  other v2: 1708.05,1339.05 1759.23,1339.05 1810.41,1339.05 1861.59,1339.05 1912.77,1339.05 1963.95,1339.05 1708.05,1390.23 1759.23,1390.23 1810.41,1390.23 1861.59,1390.23 1912.77,1390.23 1963.95,1390.23 1708.05,1441.41 1759.23,1441.41 1810.41,1441.41 1861.59,1441.41 1912.77,1441.41 1963.95,1441.41 1708.05,1492.59 1759.23,1492.59 1810.41,1492.59 1861.59,1492.59 1912.77,1492.59 1963.95,1492.59 1912.77,1542.79 1963.95,1542.79 1708.05,1543.77 1759.23,1543.77 1810.41,1543.77 1862.57,1543.77 1708.05,1594.95 1759.23,1594.95 1810.41,1594.95 1862.57,1594.95 1912.77,1594.95 1963.95,1594.95 2856,1794.36 2818.6,1817 2893.4,1817 2856,1839.64
GTX_CLK: J8.5 R100.1 U1.40 | length 2329.7
  Top Layer w5.4: U1.40@2056.54,1457.16 2090.93,1457.16 2103.72,1444.37 2118.99,1444.37 2131.11,1432.25 2131.11,1411.89 2135.71,1407.29 2140.34,1407.29 2147.48,1400.15 2151.73,1400.15 v1(2165.67,1386.21)
  Bottom Layer w5.4: v1(2165.67,1386.21) 2182.1,1402.64 2224.58,1402.64 2253.32,1373.9 2269.44,1373.9 2316,1327.34 2316,922.26 2372.52,865.74 2380.14,865.74 2418.77,904.37 2426.39,904.37 2434.05,896.71 2434.05,889.09 2395.42,850.46 2395.42,842.84 2403.08,835.18 2410.7,835.18 2449.33,873.81 2456.95,873.81 2464.61,866.15 2464.61,858.53 2425.98,819.9 2425.98,812.28 2433.64,804.62 2441.26,804.62 2479.89,843.25 2487.51,843.25 2495.17,835.59 2495.17,827.97 2456.54,789.34 2456.54,781.72 2464.2,774.06 2471.82,774.06 2510.45,812.69 2518.07,812.69 2525.73,805.03 2525.73,797.41 2487.1,758.78 2487.1,751.16 2536.26,702 2536.26,640.6 2530.86,635.2 2495.4,635.2 2490,629.8 2490,619 2495.4,613.6 2530.86,613.6 2536.26,608.2 2536.26,596.8 2503.6,564.14 2503.6,544.6 2502,543 2502,481.65 2594.65,389 2594.65,300.65 2556,262 2496,262 J8.5@2446,312 2476,342 R100.1@2476,382
GTX_CLK_EMB: J13.14 R100.2 | length 2539.4
  Top Layer w5.4: v1@2566,382 2568.79,384.79 2568.79,409.21 2628.88,469.3 2950.12,469.3 3015.69,534.87 3015.69,536.13 3056.86,577.3 3115.14,577.3 3116.14,576.3 3159.58,576.3 3171.7,588.42 3171.7,601.98 3187.42,617.7 3220.3,617.7 v1@3241,597
  Bottom Layer w5.4: R100.2@2516,382 v1@2566,382 ; J13.14@3236.36,640.8 3236,641.16 3236,669 3228,677 3197,677 3185,689 3185,710 3194.68,719.68 3253.43,719.68 3258.83,714.28 3258.83,696.4 3264.23,691 3275.03,691 3280.43,696.4 3280.43,714.28 3285.83,719.68 3297.23,719.68 3302.63,714.28 3302.63,689.4 3308.03,684 3318.83,684 3324.23,689.4 3324.23,714.28 3329.63,719.68 3434.42,719.68 3439.82,714.28 3439.82,711.67 3445.22,706.27 3456.02,706.27 3461.42,711.67 3461.42,714.28 3466.82,719.68 3477.62,719.68 3483.02,714.28 3483.02,711.67 3488.42,706.27 3499.22,706.27 3504.62,711.67 3504.62,714.28 3510.02,719.68 3549.32,719.68 3566,703 3566,649.78 3560.6,644.38 3552.4,644.38 3547,638.98 3547,628.18 3552.4,622.78 3560.6,622.78 3566,617.38 3566,605 3532.3,571.3 3504.1,571.3 3498.7,576.7 3498.7,599.6 3493.3,605 3482.5,605 3477.1,599.6 3477.1,576.7 3471.7,571.3 3424.58,571.3 3409.58,556.3 3362.28,556.3 3356.88,550.9 3356.88,529.2 3351.48,523.8 3340.68,523.8 3335.28,529.2 3335.28,586 3330.28,591 3318.68,591 3313.68,586 3313.68,529.2 3308.28,523.8 3297.48,523.8 3292.08,529.2 3292.08,550.9 3286.68,556.3 3275.88,556.3 3270.48,550.9 3270.48,529.2 3265.08,523.8 3254.28,523.8 3248.88,529.2 3248.88,550.9 3243.48,556.3 3232.68,556.3 3227.28,550.9 3227.28,529.2 3221.88,523.8 3211.08,523.8 3205.68,529.2 3205.68,550.9 3200.28,556.3 3189.48,556.3 3184.08,550.9 3184.08,529.2 3178.68,523.8 3167.28,523.8 3148.61,542.47 3148.61,556.61 3164,572 3216,572 v1@3241,597
  other v1: 2568,381 3243,596
INT_PWDN: J9.27 R14.1 R39.2 U1.60 | length 1333
  Top Layer w8: v1@1762.57,1762.27 1762.57,1741.27 1763.94,1739.9 1763.94,1733.22 1767.12,1730.04 U1.60@1767.12,1687.54 ; R14.1@2041,2317 2041,2354.46 2046,2359.46 J9.27@2046,2399
  Mid-Layer 1 w5: v1@1762.57,1762.27 1762.57,1734.43 1780.72,1716.28 2016.72,1716.28 2106.72,1806.28 2106.72,2292.72 2141,2327 2141,2347 2089,2399 J9.27@2046,2399
  Bottom Layer w5.4: R39.2@2041,2317 2041,2355.76 2046,2360.76 J9.27@2046,2399
  other v1: 1764.57,1761.27
INT_PWDN_EMB: J11.10 R39.1 | length 2098.2
  Top Layer w5.4: v1@2111,2342 2146.1,2342 2173.7,2314.4 2446.99,2314.4 2656.3,2105.09 2656.3,2097.98 2707.98,2046.3 2932.76,2046.3 2983.16,2096.7 3525.58,2096.7 3541.7,2080.58 3541.7,1970.82 3500.08,1929.2 3447.58,1929.2 3404.68,1886.3 3316.7,1886.3 v1@3296,1907
  Bottom Layer w5.4: R39.1@2081,2317 2102.7,2317 2111,2325.3 v1@2111,2342 ; J11.10@3287.55,1967.58 3287.55,1915.45 v1@3296,1907
  other v1: 3298,1906 2113,2341
IOVDD_EMB: J11.4 J11.6 J13.3 J13.5 R22.2 R57.1 | length 1827.8
  Top Layer w15: R57.1@3426,2072 3426,2044.4 3438.4,2032 v1@3451,2032
  Top Layer w20: R22.2@3376,792 v1@3376,842
  Mid-Layer 1 w20: v1@3376,842 3376,937 3401,962 3401,1088 3450,1137 3526,1137 3621,1232 3621,1442 3546,1517 3546,1832 3441,1937 3441,1946.52 3440.22,1947.3 3422.84,1973.23 3421,1975.07 3421,2002 v1@3451,2032
  Bottom Layer w15: J11.4@3382.01,1967.78 3350.55,1967.78 3350.55,1996.62 3375.43,2021.5 3396.57,2021.5 3402.07,2027 3421.5,2027 3426.5,2032 v1@3451,2032
  Bottom Layer w20: J13.5@3362.36,790.8 3362.36,828.36 3376,842 3393.36,824.64 J13.3@3393.36,790.8
  other v1: 3378,841 3453,2031
JTAG_CLK: P1.6 R104.2 R922.2 U1.25 | length 3914.8
  Top Layer w5.4: U1.25@1845.84,1246.46 1845.84,1206.12 1835.3,1195.58 1835.3,1178.42 1836.7,1177.02 1836.7,1168.42 1831.94,1163.66 1831.94,1146.06 1846,1132 v1@1846,1107 ; R922.2@3036,132 3034,132 2994.26,171.74 2994.26,173.14 2989.8,177.6 2989.8,265.8 P1.6@3036,312 3036,407 3086,457 v1@3086,507
  Bottom Layer w5.4: v1@1846,1107 1810.3,1071.3 1703.38,1071.3 1398.63,766.55 1398.63,176.77 1436,139.4 1496.34,139.4 1534.34,101.4 2660.4,101.4 2711.03,152.03 2711.03,323.32 2769.24,381.53 2769.24,487.7 2794.77,513.23 2949.77,513.23 2956,507 v1@3086,507 ; P1.6@3036,312 R104.2@3036,407
  other v1: 3088,506 1848,1106
JTAG_CLK_EMB: J13.31 R104.1 | length 869.7
  Top Layer w5.4: v1(2991,742) 3026.66,706.34 3026.66,684.78 3053.45,657.99 3279.37,657.99 3321.5,615.86 3321.5,578.14 3235.68,492.32 3166.32,492.32 v1@3096,422
  Bottom Layer w5.4: J13.31@2953.36,790.8 2953.36,759.64 2971,742 v1(2991,742) ; R104.1@3036,447 3071,447 v1@3096,422
  other v1: 3098,421
JTAG_TDI: P1.10 R109.2 R924.2 U1.28 | length 5217.6
  Top Layer w5.4: v1(1901,1192) 1904.88,1195.88 U1.28@1904.88,1246.46 ; R924.2@3236,132 3234,132 3191.76,174.24 3191.76,175.64 3186,181.4 3186,262 P1.10@3236,312
  Bottom Layer w5.4: v1(1901,1192) 1848.3,1244.7 1597.7,1244.7 1559.8,1206.8 1535.72,1206.8 1475.18,1146.26 1475.18,1043.08 1443.1,1011 1443.1,959.59 1071.45,587.94 785.04,587.94 668.57,471.47 668.57,152 793.57,27 3156.76,27 3191.76,62 3191.76,190.9 3189.8,192.86 3189.8,265.8 P1.10@3236,312 R109.2@3236,407
JTAG_TDI_EMB: J13.35 R109.1 | length 1040.6
  Top Layer w5.4: v1@2886,752 2917.74,783.74 3226.48,783.74 3288.22,722 3410.28,722 3430.3,701.98 3430.3,516.3 3406,492 3316,492 v1@3271,447
  Bottom Layer w5.4: v1@2886,752 2890.36,756.36 J13.35@2890.36,790.8 ; R109.1@3236,447 v1@3271,447
  other v1: 3273,446 2888,751
JTAG_TDO: P1.8 R103.2 R923.2 U1.26 | length 5025.7
  Top Layer w5.4: v1@1856,1187 1865.52,1196.52 U1.26@1865.52,1246.46 ; R923.2@3136,132 3134,132 3096.7,169.3 3096.7,170.58 3089.8,177.48 3089.8,265.8 P1.8@3136,312
  Bottom Layer w5.4: v1@1856,1187 1810.7,1232.3 1603.76,1232.3 1565.86,1194.4 1540.86,1194.4 1488.6,1142.14 1488.6,1038.96 1455.5,1005.86 1455.5,954.45 1075.23,574.18 788.82,574.18 680.97,466.33 680.97,157.14 798.71,39.4 3059.1,39.4 3096.7,77 3096.7,185.96 3089.8,192.86 3089.8,265.8 P1.8@3136,312 R103.2@3136,407
  other v1: 1858,1186
JTAG_TDO_EMB: J13.37 R103.1 | length 917.9
  Top Layer w5.4: v1@2851,752 2871.7,731.3 2951.02,731.3 2991.06,771.34 3183.56,771.34 3333.9,621 3333.9,559.9 3251,477 3206,477 v1@3176,447
  Bottom Layer w5.4: v1@2851,752 2858.36,759.36 J13.37@2858.36,790.8 ; R103.1@3136,447 v1@3176,447
  other v1: 3178,446 2853,751
JTAG_TMS: P1.4 R110.2 R921.2 U1.27 | length 4818.8
  Top Layer w5.4: v1@1861.27,1155.43 1880.3,1174.46 1880.3,1200.5 1885.2,1205.4 U1.27@1885.2,1246.46 ; R921.2@2936,132 2934,132 2889.8,176.2 2889.8,265.8 P1.4@2936,312
  Bottom Layer w5.4: v1@1861.27,1155.43 1858.29,1155.43 1835.3,1178.42 1835.3,1185.53 1800.93,1219.9 1608.9,1219.9 1571,1182 1546,1182 1501,1137 1501,1033.82 1467.9,1000.72 1467.9,949.31 1076.49,557.9 790.08,557.9 693.37,461.19 693.37,162.28 803.85,51.8 2854.6,51.8 2889.8,87 2889.8,265.8 P1.4@2936,312 R110.2@2936,407
  other v1: 1863.27,1154.43
JTAG_TMS_EMB: J13.39 R110.1 | length 1088.6
  Top Layer w5.4: v1@2816,747 2855.3,707.7 2994.58,707.7 3006.7,695.58 3006.7,687.2 3050.63,643.27 3276.55,643.27 3309.1,610.72 3309.1,583.28 3252.52,526.7 3095.58,526.7 3094.58,527.7 3077.42,527.7 3065.3,515.58 3065.3,508.76 3032.27,475.73 3032.27,463.27 v1@2996,427
  Bottom Layer w5.4: v1@2816,747 2827.36,758.36 J13.39@2827.36,790.8 ; R110.1@2936,447 2976,447 v1@2996,427
  other v1: 2998,426 2818,746
JTAG_TRST_N: C319.2 R36.2 U1.24 | length 478.5
  Top Layer w5.4: C319.2@1496,1117 1526.46,1117 1527.42,1116.04 1594.04,1116.04 1611,1133 v1@1611,1192 ; v1@1814.65,1176.9 1814.65,1196.6 1826.16,1208.11 U1.24@1826.16,1246.46
  Bottom Layer w5.4: v1@1611,1192 1721.64,1192 1737.14,1207.5 1784.05,1207.5 v1@1814.65,1176.9
  other v1: 1816.65,1175.9 1613,1191
JTAG_TRSTN: P1.2 R36.1 R106.2 R920.2 | length 3992
  Top Layer w5.4: R920.2@1496,1157 1515.74,1157 1536,1136.74 1556.26,1157 R36.1@1571,1157
  Bottom Layer w5.4: v1@1536,1136.74 1515.74,1116.48 1515.74,1031.02 1480.3,995.58 1480.3,944.17 1070.27,534.14 783.86,534.14 705.77,456.05 705.77,172 813.57,64.2 2675.82,64.2 2748.23,136.61 2748.23,224.23 P1.2@2836,312 R106.2@2836,407
  other v1: 1538,1135.74
JTAG_TRSTN_EMB: J13.33 R106.1 | length 1037
  Top Layer w5.4: v1@2881,422 2961,422 3052.9,513.9 3052.9,520.72 3072.28,540.1 3099.72,540.1 3100.72,539.1 3247.38,539.1 3296.7,588.42 3296.7,605.58 3271.41,630.87 3042.13,630.87 v1@2986,687
  Bottom Layer w5.4: R106.1@2836,447 2856,447 v1@2881,422 ; J13.33@2921.36,790.8 2923.83,788.33 2923.83,749.17 v1@2986,687
  other v1: 2883,421 2988,686
LED0_EMB: J11.12 R41.2 | length 2075.7
  Top Layer w5.4: v1(2191,2362) 2226.2,2326.8 2471.28,2326.8 2613.83,2184.25 2733.75,2184.25 2805.95,2112.05 3416.77,2112.05 3443,2138.28 3501.54,2138.28 3554.1,2085.72 3554.1,1965.68 3505.22,1916.8 3452.72,1916.8 3409.82,1873.9 3279.1,1873.9 v1@3246,1907
  Bottom Layer w5.4: R41.2@2186,2332 2186,2357 v1(2191,2362) ; v1@3246,1907 3255.55,1916.55 J11.12@3255.55,1967.58
  other v1: 3248,1906
LED1_EMB: J11.14 R44.2 | length 2088.8
  Top Layer w5.4: v1(2291,2372) 2323.8,2339.2 2476.42,2339.2 2618.97,2196.65 2738.89,2196.65 2811.09,2124.45 3411.63,2124.45 3437.86,2150.68 3506.68,2150.68 3566.5,2090.86 3566.5,1960.54 3510.36,1904.4 3457.86,1904.4 3414.96,1861.5 3241.5,1861.5 v1@3196,1907
  Bottom Layer w5.4: R44.2@2286,2332 2286,2367 v1(2291,2372) ; v1@3196,1907 3224.55,1935.55 J11.14@3224.55,1967.58
  other v1: 3198,1906
LED2_EMB: J11.16 R40.2 | length 2109
  Top Layer w5.4: v1@2396,2382 2409.94,2368.06 2409.94,2367.66 2426,2351.6 2506.4,2351.6 2648.95,2209.05 2744.03,2209.05 2816.23,2136.85 3406.49,2136.85 3432.72,2163.08 3511.82,2163.08 3578.9,2096 3578.9,1955.4 3515.5,1892 3463,1892 3420.1,1849.1 3203.9,1849.1 v1@3146,1907
  Bottom Layer w5.4: R40.2@2386,2332 2386,2372 v1@2396,2382 ; v1@3146,1907 3163.36,1907 3192.55,1936.19 J11.16@3192.55,1967.58
  other v1: 3148,1906 2398,2381
LED_0: J9.29 J16.2 R41.1 U1.63 | length 2145.1
  Top Layer w5.4: J16.2@1026,2022 1081,1967 1081,1877 1126,1832 1336,1832 1446,1722 1606,1722 1631,1697 1644.94,1710.94 1659.94,1710.94 1680,1731 1695.66,1731 1703.6,1723.06 1703.6,1721.86 1708.08,1717.38 U1.63@1708.08,1687.54
  Mid-Layer 1 w5.4: v1@1631,1697 1651,1697 1658.06,1704.06 2018.93,1704.06 2118.93,1804.06 2118.93,2286.64 2170.14,2337.85 2170.14,2374.86 J9.29@2146,2399
  Bottom Layer w5.4: R41.1@2146,2332 J9.29@2146,2399
  other v1: 1633,1696
LED_1: J9.31 J23.2 R44.1 U1.62 | length 1990.9
  Top Layer w5.4: J23.2@1376,2022 1426,1972 1426,1782 1452.06,1755.94 1619.06,1755.94 1641,1734 1660.7,1734 1668.1,1741.4 1715.1,1741.4 1727.76,1728.74 U1.62@1727.76,1687.54
  Mid-Layer 1 w5.4: v1@1641,1734 1607.3,1700.3 1607.3,1687 1619.15,1675.15 1639.15,1675.15 1646,1682 1656,1682 1665.71,1691.71 2021.29,1691.71 2131.29,1801.71 2131.29,2284.29 2190.3,2343.3 2198.75,2343.3 2219.66,2364.21 2219.66,2372.66 J9.31@2246,2399
  Bottom Layer w5.4: R44.1@2246,2332 J9.31@2246,2399
  other v1: 1643,1733
LED_2: J9.33 J22.2 R40.1 U1.61 | length 2847.4
  Top Layer w5.4: v1@1706,1762 1731,1762 1747.44,1745.56 U1.61@1747.44,1687.54
  Mid-Layer 1 w5.4: v1@1706,1762 1696,1762 1695.58,1761.58 1640.29,1761.58 1596.9,1718.19 1596.9,1682.69 1646.41,1633.18 1667.18,1633.18 1710.85,1676.85 2021.14,1676.85 2141.69,1797.4 2141.69,2279.98 2194.61,2332.9 2216.9,2332.9 2226,2342 2289,2342 J9.33@2346,2399
  Bottom Layer w5.4: J22.2@676,2022 941,1757 1701,1757 v1@1706,1762 ; R40.1@2346,2332 J9.33@2346,2399
  other v1: 1708,1761
MDC: R73.1 R108.2 U1.20 | length 1438.8
  Top Layer w5.4: R73.1@746,432 v1@746,467 ; v1@1696,1152 1723.56,1179.56 1723.56,1191.76 1747.44,1215.64 U1.20@1747.44,1246.46
  Bottom Layer w5.4: R108.2@746,432 746,467 781,502 1055.67,502 1705.67,1152 v1@1696,1152
  other v1: 748,466 1698,1151
MDC_EMB: J13.11 R108.1 | length 4070.6
  Top Layer w5.4: v1@786,392 796,382 796,202 851,147 v1@1561,147
  Bottom Layer w5.4: R108.1@746,392 v1@786,392 ; v1@1561,147 1579.3,128.7 1579.3,127.98 1584.98,122.3 1585.7,122.3 1594.2,113.8 2655.26,113.8 2698.63,157.17 2698.63,328.46 2756.84,386.67 2756.84,492.84 2791,527 2933.04,527 2944.98,538.94 3117.06,538.94 3157,499 3361.76,499 3394.26,531.5 3419.86,531.5 3434.86,546.5 3589.5,546.5 3646,603 3646,736 3637.52,744.48 3284.88,744.48 3267.36,762 J13.11@3267.36,790.8
  other v1: 1563,146 788,391
MDIO: R77.1 R107.2 R651.2 U1.21 | length 1351.8
  Top Layer w8: R77.1@846,432 886,432 v1@886,467 ; v1(1729.16,1143.9) 1729.16,1168.45 1751.11,1190.4 1751.11,1196.32 1767.12,1212.33 U1.21@1767.12,1246.46
  Bottom Layer w5.4: R107.2@886,432 886,467 1052.26,467 v1(1729.16,1143.9)
  other v1: 888,466
MDIO_EMB: J13.9 R107.1 | length 3902.2
  Bottom Layer w5.4: R107.1@886,392 886,390 909,367 1150.6,367 1156,361.6 1156,358.9 1186.23,328.67 1186.23,314.87 1229.33,271.77 1271.49,271.77 1282.42,282.7 1299.58,282.7 1330.05,252.23 1362.67,252.23 1386.23,228.67 1386.23,195.33 1386,195.1 1386,157 1416,127 1491.2,127 1529.2,89 2665.54,89 2723.43,146.89 2723.43,318.18 2781.64,376.39 2781.64,477.64 2796,492 3071.72,492 3077.42,486.3 3308,486.3 ; J13.9@3299.36,790.8 3299.36,763.4 3305.88,756.88 3643.12,756.88 3660,740 3660,599.46 3594.64,534.1 3440,534.1 3425,519.1 3399.4,519.1 3366.9,486.6 3334.3,486.6 ; 3308,486.3 3308.3,486.6 3334.3,486.6 ; 3308,486.3 3334,486.3 3334.3,486.6
NetC1_1: C1.1 J2.1 | length 1293.8
  Top Layer w4.1: C1.1@2231,1532 2274,1532 2279,1527 2279,1524 v1@2286,1517
  Bottom Layer w4.1: v1@2286,1517 2301,1532 2311,1532 2319.85,1523.15 2319.85,1378.15 2351,1347 2365,1347 2380,1332 2380,1280 2391,1269 2449,1269 2458,1278 2458,1340 2465,1347 2734,1347 2744,1337 2744,1296 2734,1286 2504,1286 2491,1273 J2.1@2491,1107
  other v1: 2288,1516
NetC2_1: C2.1 J3.1 | length 1294.2
  Top Layer w4.1: C2.1@2231,1562 2246,1547 2281,1547 v1@2286,1552
  Bottom Layer w4.1: v1@2286,1552 2294.9,1543.1 2315.6,1543.1 2330.95,1527.75 2330.95,1382.75 2355.6,1358.1 2369.6,1358.1 2391.1,1336.6 2391.1,1284.6 2395.6,1280.1 2444.4,1280.1 2446.9,1282.6 2446.9,1344.6 2460.4,1358.1 2732,1358.1 2742,1368.1 2742,1419 2732,1429 2508,1429 2491,1446 J3.1@2491,1607
  other v1: 2288,1551
NetC3_1: C3.1 J6.1 | length 1280.4
  Top Layer w4.1: C3.1@2191,1372 2206.06,1372 v1@2216,1381.94
  Bottom Layer w4.1: v1@2216,1381.94 2216,1347 2222.95,1340.05 2279.31,1340.05 2289.91,1329.45 2289.91,905.91 2254.9,870.9 2122.6,870.9 2090.1,838.4 2090.1,587.9 2096,582 J6.1@2321,582
  other v1: 2218,1380.94
NetC4_1: C4.1 J7.1 | length 1280.5
  Top Layer w4.1: C4.1@2191,1302 2206.06,1302 v1@2216,1292.06
  Bottom Layer w4.1: J7.1@1821,582 2067,582 2079,594 2079,843 2118,882 2250.3,882 2278.81,910.51 2278.81,1324.85 2274.71,1328.95 2222.95,1328.95 2216,1322 v1@2216,1292.06
  other v1: 2218,1291.06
